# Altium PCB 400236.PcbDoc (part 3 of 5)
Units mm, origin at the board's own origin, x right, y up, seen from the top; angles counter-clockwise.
Board outline 136.53 x 63.5 mm, 4 copper layers (Top Layer, Mid-Layer 1, Mid-Layer 2, Bottom Layer), stack 1.505 mm thick; 340 components, 230 nets, 1369 pads, 1292 vias.
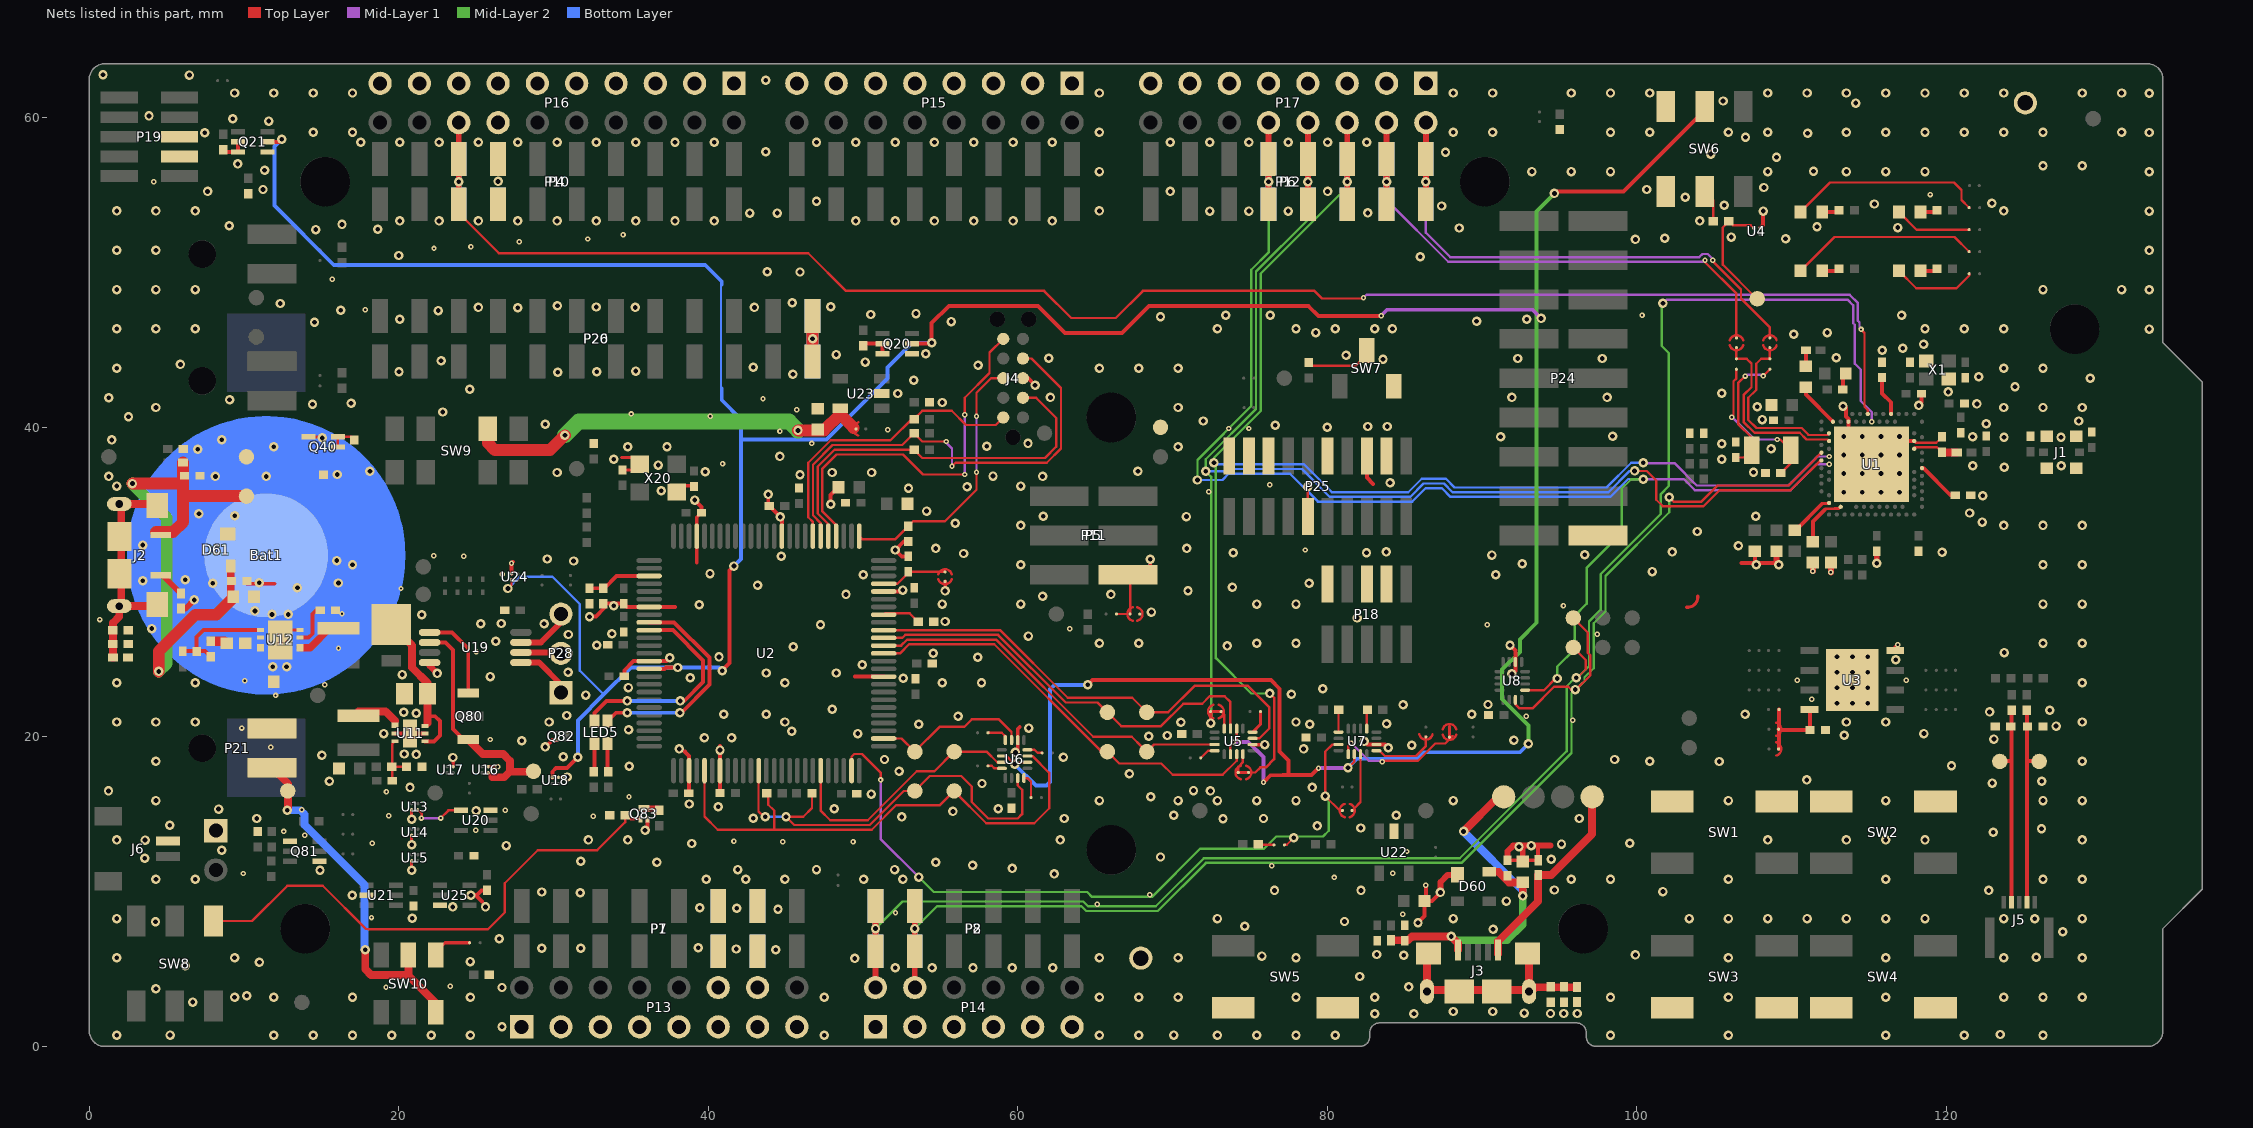
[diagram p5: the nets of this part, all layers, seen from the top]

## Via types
v1: diameter 0.61, hole 0.305, Top Layer to Bottom Layer, tented both sides, 1088 vias
v2: diameter 0.35, hole 0.15, Top Layer to Mid-Layer 1, tented both sides, 180 vias
v3: diameter 0.61, hole 0.305, Top Layer to Bottom Layer, 24 vias

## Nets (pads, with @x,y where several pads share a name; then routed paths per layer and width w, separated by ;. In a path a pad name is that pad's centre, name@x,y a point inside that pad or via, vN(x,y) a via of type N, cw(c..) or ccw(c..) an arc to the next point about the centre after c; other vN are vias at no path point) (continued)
GND: Bat1.2 C1.2 C2.2 C3.1 C4.1 C5.2 C6.2 C7.2 C8.2 C9.2 C10.1 C11.2 C12.2 C13.2 C14.2 C15.1 C16.2 C17.1 C18.1 C19.2 C20.2 C21.2 C22.2 C23.2 C24.1 C25.1 C26.1 C27.1 C28.1 C29.2 C30.2 C31.1 C32.2 C33.1 C34.1 C35.1 C36.1 C37.1 C38.1 C39.1 C40.1 C41.1 C42.1 C43.1 C44.1 C45.1 C46.2 C47.1 C48.1 C49.1 C50.1 C51.1 C52.2 C60.1 C61.1 C62.1 C63.2 C64.1 C65.1 C66.1 C67.1 C68.1 C69.1 C80.1 C82.1 C83.1 C84.1 C85.1 C86.1 C88.1 C89.1 C90.1 C91.1 C92.1 C93.1 D60.1 D61.1 FB62.2 FB63.2 FB64.2 FB65.2 J1.2 J4.3 J6.1 P1.6 P1.7 P4.7 P7.6 P7.7 P10.7 P13.1 P13.3 P13.5 P13.7 P13.9 P13.11 P13.12 P13.13 P13.14 P13.15 P14.1 P14.3 P14.5 P14.7 P14.9 P14.11 P15.1 P15.3 P15.5 P15.7 P15.9 P15.11 P15.13 P15.15 P16.1 P16.3 P16.5 P16.7 P16.9 P16.11 P16.13 P16.14 P16.15 P16.17 P16.19 P17.1 P17.3 P17.5 P17.7 P17.9 P17.11 P17.13 P17.15 P18.3 P18.5 P18.9 P19.3 P19.5 P21.1 P24.18 P25.3 P25.5 P25.9 P25.15 P25.17 P25.19 P27.1 Q20.1 Q21.1 Q40.1 Q81.1 Q81.4 Q82.2 Q83.2 R23.1 R25.1 R26.2 R27.1 R30.1 R40.2 R62.1 R63.1 R67.2 R81.1 R84.1 R85.2 R88.2 R92.2 R94.2 SB30.2 SB32.1 SW1.1 SW2.1 SW3.1 SW4.1 SW5.1 SW6.1 SW6.4 SW7.1 TP12.1 TP39.1 TP40.1 TP41.1 U1.74 U1.B7 U1.F23 U2.3 U2.7 U2.35 U2.46 U2.61 U2.72 U2.82 U2.89 U3.4 U3.9 U4.B1 U5.6 U6.6 U7.6 U8.6 U11.2 U11.5 U11.7 U12.4 U12.8 U12.9 U12.11 U13.B1 U14.B1 U15.B1 U16.B1 U17.B1 U18.B1 U19.4 U20.3 U21.2 U22.2 U23.2 U24.B1 U25.3 X1.2 X1.4 X20.2 X20.4 | length 91.7
  Top Layer w0.145: U1.F23@117.914,39.117 118.019,39.012 119.335,39.012 C3.1@119.715,39.393
  Top Layer w0.203: U12.11@12.344,25.984 U12.11@12.994,26.634 ; U12.11@12.994,26.914 U12.4@13.614,26.914 ; Q40.1@14.163,39.385 15.047,39.385 v3@15.062,39.37 ; v1(20.831,11.382) U15.B1@20.831,11.992 ; v1(20.831,13.033) U14.B1@20.831,13.643 ; v1(20.831,14.684) U13.B1@20.831,15.294 ; U17.B1@23.517,18.082 v1@23.517,18.691 ; U16.B1@25.778,18.082 v2(26.387,18.082) ; U18.B1@30.319,17.386 30.859,17.386 v1(30.884,17.412) ; 34.392,38.049 35.145,38.049 X20.2@35.575,37.619 35.21,37.254 C29.2@34.458,37.254 ; 103.207,28.382 ccw(c103.276,29.032) 103.927,29.1
  Top Layer w0.229: v1(43.866,35.67) 43.866,34.999 C34.1@43.94,34.925 ; v1(55.296,29.436) SB30.2@55.296,30.045 ; U5.6@75.157,19.507 v1(75.946,19.507)
  Top Layer w0.25: U11.2@19.751,20.218 U11.7@20.726,20.218 U11.5@21.701,20.218 ; U24.B1@27.283,30.553 v2(27.283,31.22) v2@27.381,31.318 ; v1(82.372,19.71) 82.572,19.51 U7.6@83.165,19.51 83.715,19.51 v1(83.922,19.304) ; P25.5@82.55,38.145 82.55,36.754 82.956,36.347 ; U4.B1@107.944,52.881 107.948,52.881 108.15,53.083 v1@108.15,53.997 ; v1@113.506,41.26 113.506,40.699 113.664,40.541 U1.B7@113.664,40.367 U1.74@113.664,39.117 ; U1.74@115.164,37.617 116.664,39.117 U1.F23@117.914,39.117
  Top Layer w0.254: C65.1@10.193,29.997 10.193,29.896 11.966,29.896 ; v1(24.663,9.779) 24.968,9.779 ; 25.375,9.373 24.968,9.779 ; C90.1@25.705,10.092 25.357,10.092 25.044,9.779 24.968,9.779 ; v1(29.464,19.355) 29.925,19.816 Q82.2@30.155,19.816 ; v1@32.451,27.788 32.731,27.788 33.289,28.346 33.289,28.608 C28.1@34.534,28.608 34.742,28.4 37.843,28.4 ; C25.1@34.604,23.9 C25.1@34.577,23.927 34.577,24.309 35.168,24.9 37.295,24.9 v1(37.516,25.121) ; v1(35.916,13.97) 36.064,14.119 Q83.2@36.064,14.687 ; X20.4@37.963,36.228 C30.2@39.081,36.228 ; 38.506,19.05 38.506,19.025 38.754,18.777 U2.3@38.754,17.825 ; C31.1@38.742,16.358 U2.3@38.742,17.813 ; v1(39.116,35.306) 39.555,34.867 C32.2@39.555,34.493 39.254,34.192 39.254,31.253 ; C33.1@40.75,16.383 40.754,16.388 U2.7@40.754,17.825 v1@40.754,19.418 ; C34.1@43.94,34.925 v1@44.6,34.265 ; U2.61@44.754,32.975 v1@44.754,34.055 ; v1(47.904,35.027) 47.904,35.635 C38.1@48.413,36.144 ; 49.481,23.9 U2.35@51.329,23.9 ; U2.46@51.329,29.4 52.479,29.4 v1(52.568,29.489) ; C44.1@52.924,31.666 52.5,31.666 v1(52.085,32.08) 52.627,32.622 R67.2@52.924,32.622 ; v1(59.842,18.999) 59.992,19.148 U6.6@59.992,19.792 59.992,20.52 60.122,20.65 ; J4.3@60.325,43.18 60.655,43.18 v1(61.112,42.723) ; v1(85.852,8.001) 86.273,8.422 C91.1@86.273,9.398 ; v2(86.36,10.414) 86.36,9.485 C91.1@86.273,9.398 ; v1(87.303,9.953) 86.748,9.398 C91.1@86.273,9.398 ; C62.1@91.632,12.032 92.544,12.032 FB62.2@93.65,12.032 ; v1(91.796,25.933) 92.148,25.581 U8.6@92.148,24.847 92.148,24.254 v1@91.973,24.079 ; FB62.2@93.614,12.033 93.614,12.979 ; 106.756,31.242 v1@109.093,31.242 ; C6.2@107.613,31.992 107.613,31.168 v1@107.664,31.117 ; C16.2@113.301,42.443 113.301,43.294 C15.1@113.489,43.481 ; U3.4@116.689,25.578 116.689,25.808 v2(116.84,25.959) ; v1(118.214,41.417) 118.389,41.592 C12.2@118.389,42.167
  Top Layer w0.381: FB63.2@5.933,28.304 6.231,28.304 v3(6.782,28.854) ; U19.4@21.993,24.806 21.993,24.591 v1(22.479,24.105) ; v1(87.303,9.953) 87.303,10.62 87.772,11.09 D60.1@88.402,11.09 ; C62.1@91.632,12.032 91.632,12.613 91.999,12.979 94.412,12.979 ; C61.1@92.544,12.032 C61.1@92.623,11.953 v1@92.623,12.979 ; C19.2@109.014,31.992 109.014,31.267 v1(109.164,31.117) ; v2@111.364,30.709 C20.2@111.364,31.267 ; v2@112.539,30.632 C21.2@112.539,31.267 ; C7.2@115.49,31.992 115.49,31.221 v1(115.494,31.217)
  Top Layer w0.635: R81.1@7.899,26.179 C83.1@8.76,26.179
  other v1: 1.772,0.723 11.932,0.723 14.472,0.723 17.012,0.723 19.552,0.723 22.092,0.723 24.632,0.723 47.492,0.723 65.272,0.723 67.812,0.723 72.892,0.723 75.432,0.723 77.972,0.723 80.512,0.723 98.292,0.723 105.912,0.723 116.072,0.723 121.152,0.723 126.232,0.723 5.223,0.737 70.079,0.737 123.463,0.774 26.67,1.27 83.052,2.12 85.592,2.12 94.412,2.134 95.275,2.134 96.139,2.134 92.71,2.159 88.138,2.261 90.678,2.261 6.696,2.87 9.392,3.187 11.932,3.187 17.012,3.187 24.632,3.187 47.492,3.187 65.272,3.187 67.812,3.187 70.352,3.187 77.972,3.187 83.052,3.187 98.292,3.187 105.912,3.187 116.072,3.187 123.692,3.187 126.232,3.187 128.772,3.187 10.185,3.277 4.309,3.734 26.67,3.81 85.261,3.847 82.093,4.521 52.07,5.08 54.458,5.08 57.099,5.08 59.639,5.08 62.255,5.08 6.214,5.207 10.998,5.436 24.613,5.486 49.454,5.69 1.772,5.727 9.392,5.727 65.272,5.727 70.352,5.727 77.972,5.727 105.912,5.727 116.072,5.727 123.692,5.727 128.772,5.727 125.806,5.766 75.768,5.842 84.938,5.893 99.898,5.918 83.185,5.944 44.348,6.248 41.808,6.299 29.235,6.35 31.75,6.35 39.345,6.375 26.492,6.96 127.508,7.417 90.703,7.569 74.651,7.772 4.283,8.052 81.102,8.077 1.772,8.267 72.892,8.267 88.132,8.267 103.372,8.267 105.912,8.267 108.452,8.267 110.992,8.267 113.532,8.267 116.072,8.267 118.612,8.267 123.692,8.267 125.705,8.255 128.772,8.267 20.879,8.28 44.501,8.865 41.834,8.941 39.446,8.966 23.495,9.017 25.603,9.017 91.567,9.398 16.993,9.779 31.725,9.931 29.235,9.982 101.676,10.008 76.581,10.084 82.169,10.084 122.733,10.084 94.666,10.109 4.312,10.807 6.852,10.807 39.872,10.807 42.412,10.807 44.952,10.807 50.032,10.807 52.572,10.807 95.752,10.807 98.292,10.807 105.912,10.807 116.072,10.807 126.232,10.807 128.772,10.807 62.357,11.151 14.91,11.379 41.91,11.43 46.99,11.43 52.032,11.43 59.639,11.506 57.074,11.709 36.678,11.897 54.686,11.913 31.75,11.963 94.463,12.09 3.581,12.167 69.215,12.243 8.56,12.675 92.38,12.903 26.949,12.979 93.167,12.979 95.123,13.081 38.938,13.117 99.543,13.132 1.772,13.347 3.607,13.335 32.252,13.347 34.792,13.347 62.732,13.347 108.452,13.347 113.532,13.347 116.072,13.347 118.612,13.347 128.772,13.347 123.012,13.843 126.136,14.072 82.149,14.115 79.35,14.249 5.207,14.3 73.254,14.707 10.82,14.732 42.901,14.742 62.992,14.732 75.87,14.732 96.266,14.732 52.502,14.834 70.079,14.935 84.455,14.935 55.804,15.189 24.994,15.24 8.357,15.342 48.133,15.367 58.725,15.367 40.64,15.494 38.772,15.666 4.312,15.887 65.272,15.887 70.352,15.887 72.892,15.887 75.432,15.887 77.972,15.887 88.132,15.887 105.912,15.887 116.072,15.887 126.232,15.887 128.772,15.887 68.58,16.129 50.521,16.307 1.245,16.51 72.441,16.51 71.349,16.535 20.726,16.739 79.019,16.739 57.683,16.993 122.961,17.018 15.519,17.145 126.162,17.145 110.973,17.221 67.208,17.628 52.324,17.78 34.9,18.11 120.32,18.136 4.312,18.427 100.832,18.427 105.308,18.415 128.772,18.427 51.384,18.542 98.552,18.542 23.499,18.673 62.941,18.694 30.632,18.72 15.037,18.821 21.133,18.872 20.345,18.898 40.754,19.152 38.115,19.228 78.461,19.228 85.446,19.456 27.94,19.761 92.05,19.787 123.063,19.863 39.751,19.939 41.504,19.939 68.453,20.041 69.647,20.091 113.386,20.117 19.025,20.218 49.647,20.218 118.542,20.218 45.392,20.365 34.849,20.472 60.706,20.574 127.076,20.701 53.594,20.828 78.867,20.828 83.82,20.853 1.772,20.967 4.312,20.967 6.852,20.967 29.712,20.967 44.952,20.967 70.536,20.955 77.972,20.967 113.532,20.967 116.072,20.967 128.772,20.967 56.134,21.336 30.861,21.387 40.996,21.463 43.739,21.463 89.332,21.463 106.985,21.463 21.133,21.539 20.32,21.59 122.784,21.615 126.67,21.717 48.006,21.793 84.887,22.073 90.373,22.098 112.919,22.173 113.919,22.173 114.919,22.173 32.08,22.708 77.673,22.758 79.705,23.114 112.919,23.173 113.919,23.173 114.919,23.173 34.839,23.19 1.772,23.507 6.852,23.507 44.952,23.507 55.112,23.507 57.652,23.507 128.772,23.507 52.593,23.8 38.837,23.825 25.908,23.901 20.218,24.028 91.923,24.079 43.739,24.13 48.26,24.13 112.919,24.173 113.919,24.173 114.919,24.173 30.937,24.181 49.952,24.663 116.713,24.994 57.404,25.146 40.691,25.171 112.919,25.173 113.919,25.173 114.919,25.173 54.526,25.41 123.723,25.451 45.494,25.826 73.533,25.883 32.791,25.933 65.272,26.047 67.812,26.047 75.432,26.047 77.972,26.047 126.232,26.047 128.772,26.047 26.264,26.187 60.681,26.518 30.963,26.619 33.772,26.67 47.246,27.248 25.298,27.305 29.388,27.305 26.619,27.331 55.296,27.457 81.915,27.686 32.324,27.762 21.488,27.889 68.631,28.067 33.899,28.473 39.421,28.55 55.112,28.587 60.192,28.587 75.432,28.587 77.972,28.587 126.232,28.587 128.772,28.587 61.595,29.083 48.895,29.21 66.015,29.21 70.993,29.439 73.863,29.667 43.18,29.794 78.816,29.921 50.013,30.48 90.881,30.48 40.107,30.556 100.99,30.683 17.012,31.127 60.192,31.127 107.714,31.117 126.232,31.127 128.772,31.127 92.583,31.191 31.293,31.369 29.591,31.496 44.719,31.674 90.627,31.75 96.622,31.775 56.49,31.852 73.914,31.902 82.525,31.902 119.71,31.928 83.795,31.953 102.286,31.953 54.686,32.182 70.917,32.182 106.553,32.36 103.886,33.274 60.192,33.667 123.692,33.667 126.232,33.667 128.772,33.667 55.956,33.807 122.301,33.884 44.643,34.214 70.891,34.239 107.68,34.258 61.646,34.265 121.488,34.468 54.102,34.595 122.339,35.592 113.364,35.817 114.564,35.817 115.764,35.817 116.964,35.817 36.957,35.916 52.934,36.068 56.718,36.17 1.772,36.207 60.192,36.207 84.049,36.424 1.27,36.83 61.595,36.83 58.395,36.855 45.923,36.932 113.364,37.017 114.564,37.017 115.764,37.017 116.964,37.017 30.226,37.084 47.996,37.084 50.546,37.084 107.528,37.103 39.802,37.135 67.759,37.17 123.739,37.416 121.689,37.517 127.422,37.517 36.769,37.567 33.899,37.948 105.486,37.948 44.628,38.125 113.364,38.217 114.564,38.217 115.764,38.217 116.964,38.217 108.664,38.617 11.932,38.747 34.792,38.747 37.332,38.747 70.352,38.747 57.988,38.786 105.486,38.938 60.655,38.964 1.448,39.192 123.714,39.367 127.397,39.367 91.186,39.395 113.364,39.417 114.564,39.417 115.764,39.417 116.964,39.417 121.681,39.395 98.425,39.421 79.985,40.005 82.601,40.056 83.871,40.056 76.632,40.132 29.464,40.206 122.57,40.234 71.984,40.411 128.549,40.411 108.087,40.506 2.54,40.691 22.835,40.996 4.312,41.287 70.352,41.287 123.692,41.287 126.232,41.287 128.772,41.287 107.764,41.342 113.313,41.368 14.427,41.504 121.964,41.517 16.916,41.554 55.109,41.61 9.068,41.783 1.27,41.91 62.103,41.935 91.923,41.935 98.069,41.935 52.248,42.189 105.486,42.215 120.114,42.292 24.587,42.469 124.426,42.617 53.264,43.053 129.286,43.18 122.089,43.267 45.466,43.434 30.277,43.561 20.015,43.586 32.791,43.586 35.306,43.637 1.772,43.827 65.272,43.827 67.812,43.827 70.352,43.827 123.692,43.827 126.232,43.827 42.901,43.891 57.429,44.018 5.893,44.069 50.14,44.221 22.733,44.298 83.591,44.399 92.304,44.45 97.765,44.45 62.001,44.475 112.878,44.501 81.204,44.653 48.26,44.704 54.042,44.759 115.845,44.992 117.164,45.117 118.516,45.364 110.134,46.025 79.248,46.126 112.293,46.126 1.772,46.367 4.312,46.367 6.852,46.367 72.892,46.367 77.972,46.367 80.512,46.367 83.052,46.367 118.612,46.367 121.152,46.367 123.692,46.367 133.096,46.355 84.201,46.38 14.554,46.787 55.702,46.838 89.637,46.863 20.066,46.99 92.888,46.99 69.215,47.142 73.431,47.244 76.302,47.244 117.094,47.244 50.495,47.295 53.416,47.356 22.555,47.549 16.256,47.574 27.686,47.727 25.146,47.752 35.281,47.752 42.977,47.752 32.766,47.777 47.904,47.803 30.251,47.854 12.344,48.006 45.415,48.057 1.772,48.907 4.312,48.907 6.852,48.907 126.232,48.907 131.312,48.907 133.096,48.895 45.923,50.038 43.815,50.063 86.004,51.029 19.99,51.105 1.772,51.447 4.312,51.447 133.096,51.435 99.898,52.146 109.601,52.197 101.803,52.222 106.096,52.299 14.63,52.781 18.644,52.807 88.519,52.883 116.84,52.908 111.633,52.959 9.042,53.035 16.332,53.111 20.066,53.34 22.606,53.34 25.146,53.34 27.686,53.34 30.226,53.34 32.766,53.34 35.306,53.34 37.846,53.34 40.386,53.34 49.53,53.34 52.07,53.34 54.61,53.34 57.15,53.34 59.69,53.34 62.23,53.34 104.064,53.34 42.672,53.848 44.45,53.848 82.601,53.858 1.772,53.987 4.312,53.987 6.852,53.987 65.272,53.987 72.39,53.975 74.93,53.975 77.47,53.975 108.15,53.975 123.692,53.987 133.096,53.975 87.376,54.305 105.639,54.356 115.341,54.432 122.936,54.483 46.99,54.61 103.124,54.864 7.645,55.245 69.85,55.245 80.01,55.245 11.227,55.372 100.635,55.372 108.204,55.499 26.416,55.89 65.272,56.527 93.212,56.527 95.752,56.527 98.292,56.527 108.452,56.527 113.532,56.527 116.072,56.527 118.612,56.527 133.096,56.515 111.404,56.54 11.328,56.617 126.232,56.908 128.772,56.908 9.601,57.023 109.017,57.455 104.775,57.658 87.63,57.785 43.713,57.81 17.551,58.42 20.066,58.42 22.606,58.42 25.146,58.42 27.686,58.42 30.226,58.42 32.766,58.42 35.306,58.42 37.846,58.42 40.386,58.42 46.99,58.42 49.53,58.42 52.07,58.42 54.61,58.42 57.15,58.42 59.69,58.42 62.23,58.42 69.85,58.42 72.39,58.42 74.93,58.42 77.47,58.42 80.01,58.42 82.55,58.42 107.01,58.75 111.023,59.004 7.467,59.03 14.472,59.067 17.012,59.067 65.272,59.067 88.132,59.067 90.672,59.067 98.292,59.067 100.832,59.067 105.912,59.067 108.452,59.067 113.532,59.067 116.072,59.067 118.612,59.067 121.152,59.067 123.692,59.067 126.232,59.067 131.312,59.067 133.096,59.055 11.608,59.792 9.271,59.944 3.861,60.122 114.144,60.957 105.562,61.087 9.392,61.607 11.932,61.607 14.472,61.607 17.012,61.607 65.272,61.607 88.132,61.607 90.672,61.607 95.752,61.607 98.292,61.607 100.832,61.607 108.452,61.607 110.992,61.607 113.532,61.607 116.072,61.607 118.612,61.607 121.152,61.607 123.692,61.607 128.772,61.607 131.312,61.607 133.096,61.595 43.713,62.433 6.477,62.763 0.889,62.789
  other v2: 19.177,3.835 23.325,3.886 18.237,8.331 84.861,8.534 52.095,8.636 65.126,9.195 68.529,9.804 80.442,10.922 9.957,11.176 84.226,11.201 76.403,11.684 85.141,12.598 18.288,13.132 44.806,13.233 49.352,13.233 41.656,13.259 13.919,13.64 12.573,13.894 24.968,13.97 32.563,14.884 19.355,14.91 26.873,15.265 13.741,15.291 34.874,16.129 19.202,16.459 11.735,19.329 25.908,19.837 9.855,20.574 95.86,21.082 92.837,21.336 111.303,22.428 12.04,22.682 15.215,23.368 10.058,23.622 110.363,23.673 117.399,23.673 24.994,25.502 16.104,25.73 97.434,26.634 63.348,27 90.322,27.254 0.686,27.584 16.332,27.965 95.25,28.473 20.142,29.591 26.68,30.505 112.522,30.632 111.354,30.709 24.206,31.674 22.25,31.699 78.562,32.08 72.339,35.839 76.276,36.297 40.919,37.643 46.685,38.964 44.628,39.751 51.587,39.853 73.635,39.929 74.93,39.929 40.132,40.716 35.027,40.869 45.72,41.148 43.536,41.859 100.33,47.244 17.831,47.6 15.697,49.581 22.276,51.562 24.663,51.664 27.788,51.994 32.207,52.172 34.493,52.451 118.948,55.042 4.166,55.88
  other v3: 11.862,24.536 12.751,24.536 4.039,27 11.811,27.915 12.852,27.915 10.708,28.144 13.452,29.642 7.976,29.921 10.988,29.959 16.104,29.947 3.454,30.084 6.212,30.151 16.002,31.394 3.454,32.395 9.398,34.3 7.087,34.427 8.153,36.83 11.43,36.83 16.027,36.957 18.136,37.16 7.01,38.583 8.56,39.202 15.062,39.319
I\F\_\O\F\F\: Q20.2 Q21.2 SW6.2 U2.90 U5.2 U5.10 U6.2 U6.10 U7.2 U18.B2 U24.B2 | length 259.6
  Top Layer w0.152: Q21.2@11.516,58.445 12.04,58.445 ; v1(27.051,29.591) 27.283,29.823 U24.B2@27.283,30.153 ; U6.10@58.967,18.767 59.26,18.767 59.66,18.367 U6.2@60.617,18.367 ; U5.2@73.732,18.882 73.732,19.478 v2(73.907,19.653) 74.132,19.878 U5.10@74.132,20.532 ; v1(81.331,18.009) 81.74,18.418 U7.2@81.74,18.885
  Top Layer w0.254: 12.04,58.445 12.268,58.445 v1(12.446,58.623) ; U18.B2@29.919,17.386 29.919,17.752 30.166,17.999 30.877,17.999 v1(31.572,18.694) ; U2.90@36.179,24.4 37.163,24.4 37.248,24.486 v1(38.024,24.486) ; v1(40.894,24.282) 41.377,24.765 41.377,30.759 v1(41.656,31.039) ; Q20.2@53.155,45.415 54.381,45.415 v1(54.432,45.466) 54.432,46.736 55.55,47.854 61.295,47.854 63.047,46.101 66.726,46.101 68.478,47.854 78.764,47.854 79.416,47.201 83.456,47.201 v2(83.469,47.214) ; v1(64.516,23.368) 64.823,23.675 76.35,23.675 76.913,23.112 76.913,19.048 77.495,18.466 77.495,17.533 ; v2(75.87,17.069) 76.327,17.526 77.128,17.526 77.135,17.533 77.495,17.533 ; v2(79.426,17.983) 78.976,17.533 77.495,17.533 ; v1(94.666,55.118) 94.793,55.245 99.129,55.245 SW6.2@104.369,60.484
  Mid-Layer 1 w0.254: v2@73.932,19.678 74.886,19.678 75.87,18.694 v2(75.87,17.069) ; v2(79.426,17.983) 81.305,17.983 v1(81.331,18.009) ; v2(83.469,47.214) 83.854,47.6 93.243,47.6 v1(93.802,47.041)
  Mid-Layer 2 w0.254: v1(92.989,19.558) 92.989,20.752 91.288,22.454 91.288,24.359 92.431,25.502 92.431,26.309 93.497,27.376 v1@93.497,47.041 ; v1(93.802,47.041) v1@93.497,47.041 ; v1(94.666,55.118) 93.497,53.95 v1@93.497,47.041
  Bottom Layer w0.152: v1(27.051,29.591) 27.805,30.345 29.929,30.345 31.699,28.575 31.699,24.272 33.238,22.733 ; 40.818,42.52 40.818,49.224
  Bottom Layer w0.254: v1(12.446,58.623) 11.963,58.141 11.963,54.331 15.799,50.495 39.802,50.495 40.869,49.428 40.869,49.224 ; v1(31.572,18.694) 31.572,21.067 33.238,22.733 34.991,24.486 v1(38.024,24.486) 40.691,24.486 v1(40.894,24.282) ; 40.869,42.52 40.869,41.758 42.113,40.513 42.113,39.268 ; v1(41.656,31.039) 42.113,31.496 42.113,39.268 ; v1(54.432,45.466) 53.162,45.466 51.575,43.878 51.575,43.149 47.643,39.218 42.164,39.218 42.113,39.268 ; v1(59.792,18.237) 61.163,16.866 61.849,16.866 62.078,17.094 62.078,23.089 62.357,23.368 v1(64.516,23.368) ; v1(81.331,18.009) 81.915,18.593 85.827,18.593 86.245,19.011 92.443,19.011 v1(92.989,19.558)
IMCU_BOOT: SB46.2 SB65.1 U2.24 U7.15 | length 48.6
  Top Layer w0.152: U2.24@49.254,17.825 49.254,18.723 49.428,18.898 49.936,18.898 51.13,17.704 v2(51.13,17.221) ; SB65.1@77.224,13.03 77.368,13.03 v1(77.826,13.487) ; v1(79.858,16.18) v1@79.865,16.172 ; v1@79.916,16.172 v1@80.035,16.172 ; U7.15@80.715,19.51 80.326,19.51 79.865,19.05 v1@79.865,16.172 ; SB46.2@80.968,15.24 80.797,15.24 80.793,15.244 v1@79.865,16.172
  Mid-Layer 1 w0.152: v2(51.13,17.221) 51.13,13.411 v1(53.594,10.947)
  Mid-Layer 2 w0.152: v1(53.594,10.947) 54.559,9.982 64.478,9.982 64.794,9.667 68.659,9.667 71.768,12.776 75.903,12.776 76.69,13.564 79.706,13.564 80.086,13.944 80.086,15.951 v1(79.858,16.18)
IMCU_CTS: TP1.1 U2.38 U5.3 | length 27
  Top Layer w0.152: U2.38@51.329,25.4 52.389,25.4 52.973,25.984 53.67,25.984 58.471,25.984 TP1.1@65.405,19.05 ; TP1.1@65.786,19.05 66.548,18.288 69.266,18.288 70.002,17.551 73.228,17.551 74.139,18.463 U5.3@74.139,18.885
IMCU_RESET: J4.10 R66.1 U2.57 | length 19.4
  Top Layer w0.152: U2.57@46.754,32.975 46.754,33.894 46.457,34.192 46.457,37.717 47.907,39.167 51.773,39.167 R66.1@53.221,40.615 ; R66.1@53.297,40.538 53.831,41.072 55.726,41.072 56.64,40.157 58.572,40.157 J4.10@59.055,40.64
IMCU_RTS: TP3.1 U2.39 U5.15 | length 24.3
  Top Layer w0.152: U2.39@51.329,25.9 52.458,25.9 52.848,26.29 53.035,26.29 56.972,26.29 56.974,26.289 58.597,26.289 64.871,20.015 67.361,20.015 TP3.1@67.988,19.388 ; TP3.1@68.326,19.05 68.786,19.51 U5.15@72.714,19.51
IMCU_RXD: TP2.1 U2.40 U5.11 | length 27.6
  Top Layer w0.152: U2.40@51.329,26.4 52.527,26.4 52.722,26.595 58.722,26.595 63.092,22.225 65.151,22.225 TP2.1@65.786,21.59 66.675,20.701 69.247,20.701 70.695,22.149 71.907,22.149 72.39,22.631 73.355,22.631 73.732,22.254 U5.11@73.732,20.532
IMCU_TCKS: J4.4 R65.1 U2.56 | length 30.9
  Top Layer w0.152: U2.56@47.254,32.975 47.254,33.825 46.761,34.318 46.761,37.59 48.033,38.862 52.531,38.862 53.293,39.624 53.827,39.091 v2@55.397,39.091 ; v2(55.745,37.49) 55.974,37.719 61.87,37.719 62.786,38.635 62.786,42.547 60.884,44.45 J4.4@60.325,44.45
  Mid-Layer 1 w0.152: v2@55.397,39.091 55.397,38.989 55.745,38.641 v2(55.745,37.49)
  other v2: 55.372,39.091
IMCU_TDIS: J4.8 R67.1 U2.51 | length 17.4
  Top Layer w0.152: U2.51@49.754,32.975 49.963,32.766 52.068,32.766 R67.1@52.924,33.622 53.236,33.934 55.296,33.934 57.328,35.966 v2(57.328,37.109) ; v2(57.328,40.716) 57.328,42.241 58.267,43.18 J4.8@59.055,43.18
  Mid-Layer 1 w0.152: v2(57.328,37.109) v2(57.328,40.716)
IMCU_TDOS: J4.6 U2.54 | length 24.6
  Top Layer w0.152: U2.54@48.254,32.975 48.254,33.687 47.371,34.571 47.371,37.338 48.285,38.252 52.578,38.252 53.873,36.957 v2(56.566,36.957) ; v2@56.566,40.767 56.566,41.91 58.166,43.51 58.166,44.831 J4.6@59.055,45.72
  Mid-Layer 1 w0.152: v2(56.566,36.957) v2@56.566,40.767
  other v2: 56.566,40.818
IMCU_TMSS: J4.2 R64.1 U2.55 | length 25.7
  Top Layer w0.152: U2.55@47.754,32.975 47.754,33.756 47.066,34.444 47.066,37.464 48.159,38.557 53.293,38.557 53.827,38.024 61.747,38.024 62.484,38.76 62.484,40.604 61.178,41.91 J4.2@60.325,41.91
IMCU_TXD: TP4.1 U2.41 U5.7 | length 31.1
  Top Layer w0.152: U2.41@51.329,26.9 58.848,26.9 63.218,22.53 67.386,22.53 TP4.1@68.326,21.59 69.705,21.59 71.434,23.319 74.826,23.319 76.251,21.895 76.251,20.566 75.592,19.907 U5.7@75.157,19.907
N\R\F\_\O\N\L\Y\: R3.1 TP22.1 U4.B2 | length 7.9
  Top Layer w0.152: U4.B2@107.544,52.876 107.357,53.063 106.187,53.063 R3.1@105.935,53.315 105.537,52.916 105.537,50.516 107.743,48.311 TP22.1@107.772,48.311
NetC3_2: C3.2 L1.1 U1.H23 | length 2.9
  Top Layer w0.145: U1.H23@117.914,38.617 118.019,38.722 119.384,38.722 119.718,38.388 C3.2@119.723,38.383
  Top Layer w0.508: C3.2@119.718,38.388 L1.1@120.612,38.388
NetC9_1: C9.1 U1.N24 | length 2.9
  Top Layer w0.25: U1.N24@118.414,37.367 118.5,37.367 120.25,35.617 C9.1@120.564,35.617
NetC13_1: C13.1 U1.A18 | length 2.6
  Top Layer w0.25: C13.1@115.839,43.217 115.839,42.2 116.414,41.625 U1.A18@116.414,40.867
NetC17_2: C17.2 SB2.1 X2.1 | length 8.3
  Top Layer w0.152: C17.2@106.385,38.05 106.921,38.05 107.421,38.55 107.421,39.34 106.537,40.224 106.537,42.86 v2(106.995,43.317) ; v2@107.02,43.317 v2@107.045,43.291 ; v2(108.153,43.325) SB2.1@108.585,43.757
  Mid-Layer 1 w0.152: v2@107.104,43.401 108.077,43.401 v2(108.153,43.325)
NetC18_2: C18.2 SB1.1 X2.2 | length 9.6
  Top Layer w0.152: v2(106.121,40.665) 106.24,40.784 106.24,42.983 106.426,43.169 SB1.1@106.426,43.757 ; v2(109.068,39.218) 109.254,39.218 109.921,38.55 X2.2@109.921,38.525 109.921,37.675 C18.2@109.298,37.052
  Mid-Layer 1 w0.152: v2@106.147,40.665 107.594,39.218 v2(109.068,39.218)
NetC20_1: C20.1 U1.AC5 | length 3.6
  Top Layer w0.184: C20.1@111.354,32.614 C20.1@111.354,32.617 ; 112.062,34.608 112.202,34.747 112.254,34.747 112.258,34.743 112.749,34.743 112.755,34.749 113.045,34.749 U1.AC5@113.164,34.867
  Top Layer w0.254: C20.1@111.364,32.617 111.364,33.909 112.112,34.657
NetC27_2: C27.2 R25.2 U2.78 | length 4.1
  Top Layer w0.254: C27.2@32.4,29.608 33.289,29.608 34.081,30.4 U2.78@36.179,30.4
NetC44_2: C44.2 SB30.1 U2.47 | length 4.3
  Top Layer w0.152: U2.47@51.329,29.9 52.214,29.9 52.924,30.609 C44.2@52.924,30.666 54.939,30.666 55.291,30.666 SB30.1@55.296,30.67
NetC49_2: C49.2 SB16.2 SB17.2 SB18.2 U3.8 | length 6
  Top Layer w0.254: SB18.2@109.177,19.228 SB16.2@109.177,21.768 ; SB17.2@109.177,20.523 SB17.2@109.151,20.498 109.202,20.447 C49.2@111.168,20.447 ; U3.8@111.149,21.768 111.168,21.749 C49.2@111.168,20.447 ; C49.2@111.184,20.447 C49.2@111.168,20.447
NetC60_2: C60.2 C61.2 C62.2 D60.4 FB60.1 J3.1 TP15.1 | length 24.3
  Top Layer w0.508: FB60.1@84.106,6.866 85.224,6.866 85.471,7.113 v1(88,7.113) 88.429,6.684 J3.1@88.429,6.232 ; v1(88.798,13.894) TP15.1@91.034,16.129 ; D60.4@90.452,11.29 91.047,11.29 91.733,10.603 C61.2@92.623,10.603 v1(92.623,9.728)
  Mid-Layer 2 w0.508: v1(88,7.113) 88.253,6.86 91.595,6.86 92.623,7.889 v1(92.623,9.728)
  Bottom Layer w0.508: v1(88.798,13.894) 92.623,10.069 v1(92.623,9.728)
NetC63_1: C63.1 C64.2 C65.2 D61.4 FB61.1 J2.1 TP11.1 | length 36.3
  Top Layer w0.508: C64.2@9.144,28.905 D61.4@9.144,31.055
  Top Layer w0.762: v1(2.794,36.373) 5.781,36.373 6.06,36.093 ; J2.1@4.318,33.233 5.41,33.233 6.06,33.884 6.06,35.56 ; v1(4.496,24.232) 4.496,25.538 6.86,27.902 8.217,27.902 C64.2@9.297,28.981 ; FB61.1@6.06,37.734 6.06,36.093 ; TP11.1@10.16,35.56 6.06,35.56 ; 6.06,35.56 6.06,36.093
  Mid-Layer 2 w0.762: v1(2.794,36.373) 5.004,34.163 5.004,24.74 v1(4.496,24.232)
NetC66_2: C66.2 FB64.1 J3.6@86.429,3.557 J3.6@86.529,6.007 J3.6@88.529,3.557 J3.6@90.929,3.557 J3.6@92.929,6.007 J3.6@93.029,3.557 R62.2 | length 14.7
  Top Layer w0.508: J3.6@86.427,6.003 86.427,3.653 J3.6@93.027,3.653 ; J3.6@93.027,3.399 cw(c93.331,3.399) J3.6@93.029,3.434 ; J3.6@93.029,3.303 J3.6@93.029,3.434 ; J3.6@93.029,3.688 J3.6@93.029,6.003 ; J3.6@93.331,3.703 ccw(c93.331,3.399) J3.6@93.029,3.434 ; J3.6@93.331,3.83 FB64.1@96.12,3.83
NetC67_2: C67.2 FB65.1 J2.6@1.944,28.45 J2.6@1.944,30.55 J2.6@1.944,32.95 J2.6@1.944,35.05 J2.6@4.394,28.55 J2.6@4.394,34.95 R63.2 | length 15.1
  Top Layer w0.508: FB65.1@1.546,25.139 1.546,27.378 1.944,27.776 J2.6@1.944,28.45 ; J2.6@2.087,28.434 J2.6@2.071,28.45 ; J2.6@4.521,28.55 4.421,28.45 J2.6@2.071,28.45 ; J2.6@4.521,34.95 4.421,35.05 2.071,35.05 J2.6@2.071,28.45
NetC81_1: C81.1 R80.1 R81.2 U12.7 | length 7.2
  Top Layer w0.254: C81.1@6.045,25.544 R80.1@6.934,25.544 ; R80.1@6.934,25.519 R80.1@6.934,25.544 ; R81.2@7.849,25.179 7.484,25.544 R80.1@6.934,25.544 ; U12.7@11.074,26.914 7.381,26.914 6.934,26.467 R80.1@6.934,25.544
NetC84_2: C84.2 U12.3 | length 2.8
  Top Layer w0.254: U12.3@13.614,26.414 14.175,26.414 14.427,26.666 14.427,27.936 14.685,28.194 C84.2@14.918,28.194
NetC86_2: C86.2 D84.3 U11.4 U11.6 | length 10.3
  Top Layer w0.25: 21.856,21.184 21.857,21.182 21.871,21.168
  Top Layer w0.254: U11.4@21.701,19.718 22.284,19.718 22.657,20.091 22.657,21.031 22.352,21.336 21.857,21.336
  Top Layer w0.508: D84.3@19.507,27.268 20.862,25.914 20.862,24.477 21.857,23.482 C86.2@21.857,22.784 ; 21.857,20.906 21.857,21.182 21.857,21.336 C86.2@21.857,22.76
NetC87_1: C87.1 R82.1 R84.2 U11.3 | length 3.6
  Top Layer w0.152: R82.1@19.55,18.085 R82.1@19.575,18.085 ; C87.1@19.575,17.17 R82.1@19.575,18.085 ; U11.3@19.751,19.718 19.575,19.542 R82.1@19.575,18.085 ; R84.2@20.506,18.085 R82.1@19.575,18.085
NetC92_2: C92.2 SB81.2 SW9.7 U23.5 | length 26.8
  Top Layer w0.762: SW9.7@25.749,39.906 25.749,38.996 26.213,38.532 29.769,38.532 v1(30.734,39.497) ; v1(45.796,39.802) 47.473,39.802 48.51,40.839 ; U23.5@48.51,41.123 48.51,40.839 ; 49.387,39.963 48.51,40.839
  Mid-Layer 2 w1.016: v1(30.734,39.497) 31.623,40.386 45.212,40.386 v1(45.796,39.802)
NetFB62_1: FB62.1 J3.5 TP16.1 | length 13.2
  Top Layer w0.508: J3.5@91.029,5.978 91.029,6.803 93.614,9.387 FB62.1@93.614,11.083 94.457,11.083 97.104,13.73 TP16.1@97.104,16.129
NetFB63_1: FB63.1 J2.5 | length 1.8
  Top Layer w0.381: J2.5@4.619,30.45 4.737,30.45 FB63.1@5.933,29.254
NetL2_1: L2.1 L3.2 | length 1.1
  Top Layer w0.25: L2.1@110.914,43.942 L3.2@110.914,44.992
NetL2_2: L2.2 U1.B3 | length 2.9
  Top Layer w0.25: L2.2@110.914,42.592 110.914,42.117 U1.B3@112.664,40.367
NetL4_2: L4.2 U1.AB2 | length 3.1
  Top Layer w0.203: 111.957,35.063 111.98,35.087 112.383,35.087 U1.AB2@112.414,35.117
  Top Layer w0.25: L4.2@110.189,33.342 L4.2@110.236,33.342 ; L4.2@110.33,33.342 L4.2@110.236,33.342 ; 111.957,35.063 L4.2@110.236,33.342
NetL80_1: L80.1 U12.2 | length 3
  Top Layer w0.457: U12.2@13.614,25.764 14.283,25.764 15.553,27.033 L80.1@16.104,27.033
NetL81_1: L81.1 U11.1 | length 2.6
  Top Layer w0.508: L81.1@17.399,21.649 19.151,21.649 19.751,21.048
NetLED1_1: LED1.1 SB5.2 | length 12.7
  Top Layer w0.152: LED1.1@110.575,53.917 112.48,55.822 120.479,55.822 120.965,55.337 120.965,54.696 SB5.2@121.464,54.197
NetLED1_2: LED1.2 R47.1 | length 1.1
  Top Layer w0.254: LED1.2@111.972,53.917 112.932,53.917 R47.1@113.059,54.044
NetLED2_1: LED2.1 SB6.2 | length 5
  Top Layer w0.152: LED2.1@116.925,53.917 118.067,52.774 120.968,52.774 SB6.2@121.464,52.774
NetLED2_2: LED2.2 R48.1 | length 1.1
  Top Layer w0.254: LED2.2@118.322,53.917 119.257,53.917 R48.1@119.384,54.044
NetLED3_1: LED3.1 SB7.2 | length 12.2
  Top Layer w0.152: LED3.1@110.575,50.107 112.766,52.299 120.517,52.299 SB7.2@121.464,51.352
NetLED3_2: LED3.2 R50.1 | length 1.1
  Top Layer w0.254: LED3.2@111.972,50.107 112.932,50.107 R50.1@113.059,50.234
NetLED4_1: LED4.1 SB8.2 | length 5.5
  Top Layer w0.152: LED4.1@116.925,50.107 118.042,48.99 120.643,48.99 121.464,49.81 SB8.2@121.464,49.93
NetLED4_2: LED4.2 R51.1 | length 1.1
  Top Layer w0.254: LED4.2@118.322,50.107 119.257,50.107 R51.1@119.384,50.234
NetLED5_1: LED5.1 R20.1 | length 1.8
  Top Layer w0.254: R20.1@32.636,17.747 LED5.1@32.636,19.57
NetLED5_2: LED5.2 R21.1 | length 1.8
  Top Layer w0.254: R21.1@33.486,17.747 LED5.2@33.486,19.57
NetP5_6: P5.6 P11.6 SB32.2 SB33.1 | length 5.2
  Top Layer w0.152: SB33.1@66.378,27.94 67.077,27.94 ; P5.6@67.119,30.48 67.252,30.348 67.252,28.293 SB32.2@67.252,27.94
  Top Layer w0.254: P5.6@68.555,30.531 v1(68.555,31.481)
  Bottom Layer w0.254: P11.6@68.555,30.531 v1(68.555,31.481)
NetP20_12: P20.12 P26.12 | length 5.9
  Top Layer w0.762: P20.12@46.736,44.255 P20.12@46.736,47.185
  Bottom Layer w0.762: P26.12@46.736,44.255 v1(46.736,45.72) P26.12@46.736,47.185
NetP21_2: P21.2 SW10.2 SW10.4 TP27.1 | length 23.4
  Top Layer w0.508: P21.2@11.811,18.009 12.852,16.967 12.852,15.316 v1(12.802,15.265) ; v1(17.831,6.248) 17.831,5.004 18.212,4.623 20.574,4.623 ; SW10.2@20.625,5.914 20.625,4.674 20.574,4.623 ; SW10.4@22.375,2.214 22.375,2.822 20.574,4.623
  Bottom Layer w0.508: v1(12.802,15.265) 13.64,15.265 13.919,14.986 13.919,14.305 17.78,10.444 17.78,6.299 v1(17.831,6.248)
NetP28_1: P28.1 U19.5 | length 3.7
  Top Layer w0.381: U19.5@27.893,24.806 29.067,24.806 30.48,23.393 P28.1@30.48,22.86
NetP28_2: P28.2 U19.6 | length 2.6
  Top Layer w0.381: U19.6@27.893,25.456 30.424,25.456 P28.2@30.48,25.4
NetP28_3: P28.3 U19.7 | length 3.7
  Top Layer w0.381: U19.7@27.893,26.106 29.179,26.106 30.48,27.407 P28.3@30.48,27.94
NetQ20_5: Q20.5 Q20.6 R22.2 | length 2
  Top Layer w0.254: R22.2@49.996,45.271 50.14,45.415 Q20.5@51.255,45.415 Q20.6@51.255,44.765
NetQ21_5: Q21.5 Q21.6 R24.2 | length 1.7
  Top Layer w0.254: R24.2@8.661,57.945 8.811,57.795 Q21.6@9.616,57.795 Q21.5@9.616,58.445
NetQ40_5: Q40.5 Q40.6 R41.2 | length 1.8
  Top Layer w0.152: Q40.5@16.063,38.735 Q40.6@16.063,39.385 16.919,39.385 R41.2@17.12,39.184
NetQ80_1: Q80.1 U19.1 | length 5.6
  Top Layer w0.254: U19.1@22.196,26.756 23.434,26.756 24.489,25.701 Q80.1@24.489,22.836
NetQ80_3: Q80.3 TP34.1 U16.A1 U19.2 | length 15
  Top Layer w0.25: U16.A1@25.778,17.682 26.065,17.394
  Top Layer w0.254: U19.2@22.196,26.106 23.018,26.106 23.51,25.614 23.51,20.509 24.182,19.836 Q80.3@24.489,19.836
  Top Layer w0.508: Q80.3@24.489,19.836 25.427,18.898 26.746,18.898 27.178,18.466 27.178,17.755 ; 26.065,17.394 26.818,17.394 27.178,17.755 ; TP34.1@28.651,17.856 28.55,17.755 27.178,17.755
NetQ83_1: Q83.1 R94.1 SW8.4 | length 34.1
  Top Layer w0.152: SW8.4@8.028,8.109 10.522,8.109 12.802,10.389 15.088,10.389 17.882,7.595 18.001,7.595 18.026,7.569 25.756,7.569 26.851,8.664 26.851,10.544 28.981,12.675 32.817,12.675 34.638,14.495 R94.1@34.638,14.935 ; R94.1@34.714,14.961 34.988,14.687 Q83.1@35.614,14.687
NetQ83_3: Q83.3 R93.2 | length 1
  Top Layer w0.381: Q83.3@35.839,15.387 36.701,15.387 R93.2@36.83,15.257
NetR3_2: R3.2 SW6.5 | length 2.2
  Top Layer w0.152: SW6.5@104.369,55.238 104.935,54.671 R3.2@104.935,53.315
NetR4_2: R4.2 SW7.2 | length 4.4
  Top Layer w0.152: R4.2@78.791,44.188 78.985,43.994 81.84,43.994 82.55,44.704 SW7.2@82.55,44.965
NetR30_2: R30.2 U2.43 | length 2.5
  Top Layer w0.152: U2.43@51.329,27.9 51.42,27.991 53.008,27.991 R30.2@53.567,27.432
NetR49_1: R49.1 SB65.2 | length 1
  Top Layer w0.152: R49.1@75.532,13.081 75.582,13.03 SB65.2@76.548,13.03
NetR52_2: R52.2 U7.9 | length 1.2
  Top Layer w0.152: U7.9@82.54,20.535 R52.2@82.54,21.742
NetR53_2: R53.2 U7.13 | length 1.5
  Top Layer w0.152: U7.13@80.715,20.31 R53.2@80.715,21.768
NetSB42_1: SB42.1 U7.1 | length 8.6
  Top Layer w0.152: U7.1@81.34,18.885 81.34,19.415 v2(81.534,19.609) ; v2(83.541,18.39) 83.617,18.466 85.851,18.466 86.965,19.58 87.608,19.58 88.087,20.058
  Mid-Layer 1 w0.152: v2(81.534,19.609) 82.677,18.466 83.464,18.466 v2(83.541,18.39)
NetSB45_1: SB45.1 U7.5 | length 4.2
  Top Layer w0.152: U7.5@83.165,19.11 83.361,19.11 83.701,18.771 85.725,18.771 86.36,19.406 86.36,19.833 SB45.1@86.36,20.008
NetSB46_1: SB46.1 U7.3 | length 3.9
  Top Layer w0.152: SB46.1@81.592,15.24 81.741,15.389 82.14,15.788 U7.3@82.14,18.885
NetSB50_2: SB50.2 U5.16 | length 1.1
  Top Layer w0.152: SB50.2@71.813,18.644 72.28,19.11 U5.16@72.714,19.11
NetSB51_2: SB51.2 U5.4 | length 1.3
  Top Layer w0.152: SB51.2@74.237,17.704 74.237,18.077 74.539,18.38 U5.4@74.539,18.885
NetSB52_2: SB52.2 U5.8 | length 1.6
  Top Layer w0.152: U5.8@75.157,20.307 U5.8@75.164,20.314
  Top Layer w0.203: U5.8@75.164,20.31 75.164,20.314 75.674,20.824 SB52.2@75.674,21.641
NetSB53_2: SB53.2 U5.12 | length 1.2
  Top Layer w0.152: SB53.2@73.134,21.641 73.332,21.443 U5.12@73.332,20.532
NetSB54_2: SB54.2 U6.16 | length 1.6
  Top Layer w0.152: U6.16@60.392,17.342 60.628,17.342 60.851,17.119 SB54.2@60.851,16.078
NetSB55_2: SB55.2 U6.4 | length 1
  Top Layer w0.152: U6.4@60.617,19.167 61.071,19.167 61.265,18.974 SB55.2@61.562,18.974
NetSB56_2: SB56.2 U6.8 | length 1.5
  Top Layer w0.152: SB56.2@58.072,20.269 58.953,20.269 59.192,20.031 U6.8@59.192,19.792
NetSB57_2: SB57.2 U6.12 | length 1
  Top Layer w0.152: SB57.2@58.072,18.136 58.318,18.136 58.487,17.967 U6.12@58.967,17.967 U6.12@58.967,17.937
NetSB58_2: SB58.2 SW10.1 | length 2.6
  Top Layer w0.203: SW10.1@22.375,5.914 22.375,6.093 22.987,6.706 SB58.2@24.58,6.706
NetU13_B2: U13.B2 U20.4 | length 3.4
  Top Layer w0.152: U13.B2@21.231,15.294 21.488,15.037 v2@21.488,14.757 ; v2(22.708,14.757) 23.205,15.255 U20.4@24.018,15.255
  Mid-Layer 1 w0.152: v2(21.463,14.757) v2(22.708,14.757)
NFC1: C46.1 J5.2 R44.1 TP17.1 | length 12.9
  Top Layer w0.25: TP17.1@123.479,18.44 124.198,18.44 ; J5.2@124.198,9.328 124.198,18.44 ; R44.1@124.198,21.463 124.198,18.44
NFC2: C47.2 J5.4 R46.1 TP18.1 | length 12.8
  Top Layer w0.25: J5.4@125.198,9.328 125.198,18.44 ; R46.1@125.198,21.463 125.198,18.44 ; TP18.1@125.909,18.44 125.198,18.44
OB_LED1: LED5.4 U2.84 | length 14.1
  Top Layer w0.254: LED5.4@33.486,21.02 34.031,21.565 v1(34.763,21.565) ; U2.84@36.179,27.4 37.792,27.4 40.071,25.121 40.071,23.38 38.256,21.565 v1(38.166,21.565)
  Bottom Layer w0.254: v1(34.763,21.565) v1(38.166,21.565)
OB_LED2: LED5.3 U2.85 | length 14.1
  Top Layer w0.254: LED5.3@32.636,21.02 32.636,21.546 33.416,22.327 v1(34.763,22.327) ; U2.85@36.179,26.9 37.717,26.9 39.665,24.952 39.665,23.548 38.443,22.327 v1(38.192,22.327)
  Bottom Layer w0.254: v1(34.763,22.327) v1(38.192,22.327)
OB_RESET: TP7.1 U2.27 U6.7 | length 10.3
  Top Layer w0.152: U2.27@51.329,19.9 52.49,19.9 TP7.1@53.34,19.05 54.94,20.65 56.54,20.65 57.023,21.133 58.776,21.133 59.592,20.317 U6.7@59.592,19.792
OB_SWDCLK: R28.2 TP6.1 U2.5 U6.3 | length 34.6
  Top Layer w0.152: U2.5@39.754,17.825 39.754,14.856 40.604,14.006 44.256,14.006 ; R28.2@43.772,16.358 43.875,16.255 43.875,15.621 44.256,15.24 44.256,14.006 ; U6.3@60.617,18.767 60.938,18.767 62.027,17.678 62.027,15.392 61.062,14.427 57.963,14.427 TP6.1@55.88,16.51 54.966,15.596 52.145,15.596 50.555,14.006 44.256,14.006
OB_SWDIO: R29.2 TP5.1 U2.12 U6.15 | length 28.5
  Top Layer w0.152: U2.12@43.254,17.825 43.244,17.814 43.244,15.176 43.576,14.844 v1(43.678,14.844) ; R29.2@46.703,16.358 46.703,15.41 46.137,14.844 v1(45.018,14.844) 45.551,14.31 50.428,14.31 52.628,16.51 TP5.1@53.34,16.51 54.305,17.475 56.337,17.475 57.023,16.789 57.023,15.798 58.089,14.732 59.995,14.732 60.274,15.011 60.274,16.588 59.992,16.87 U6.15@59.992,17.342
  Bottom Layer w0.152: v1(43.678,14.844) v1(45.018,14.844)
OB_SWO: TP8.1 U2.20 U6.11 | length 16.7
  Top Layer w0.152: U2.20@47.254,17.825 47.254,15.24 47.879,14.615 50.302,14.615 53.467,17.78 54.61,17.78 TP8.1@55.88,19.05 57.983,19.05 58.665,18.367 U6.11@58.967,18.367
P0.00: P6.1 P12.1 P17.2 SB4.2 | length 37.6
  Top Layer w0.152: v2@104.851,50.775 106.723,48.902 106.723,48.318 108.585,46.457 108.585,45.953 SB4.2@108.585,45.778
  Top Layer w0.381: P6.1@86.36,54.415 v1(86.36,55.88) P6.1@86.36,57.345 P17.2@86.36,59.69
  Mid-Layer 1 w0.152: v1(86.36,55.88) 86.36,52.577 87.934,51.003 104.026,51.003 104.227,51.204 104.578,51.204 104.902,50.879 v2(104.902,50.8) ; v2@104.851,50.775 v2@104.851,50.8
  Bottom Layer w0.381: P12.1@86.36,54.415 v1(86.36,55.88) P12.1@86.36,57.345
P0.00/XL1: SB2.2 SB4.1 U1.D2 | length 11.2
  Top Layer w0.145: 111.1,39.512 112.309,39.512 U1.D2@112.414,39.617
  Top Layer w0.152: SB4.1@108.585,45.154 108.585,44.432 108.029,44.432 107.703,44.107 107.703,42.418 107.195,41.91 107.195,40.479 107.716,39.958 110.642,39.958 111.077,39.523
P0.01: P6.2 P12.2 P17.4 SB3.2 | length 37.4
  Top Layer w0.152: v2(104.394,50.8) 104.394,50.673 106.426,48.641 106.426,45.953 SB3.2@106.426,45.778
  Top Layer w0.381: P6.2@83.82,54.415 v1(83.82,55.88) P6.2@83.82,57.345 P17.4@83.82,59.69
  Mid-Layer 1 w0.152: v1(83.82,55.88) 83.82,54.686 87.808,50.698 v2@104.318,50.698
  Bottom Layer w0.381: P12.2@83.82,54.415 v1(83.82,55.88) P12.2@83.82,57.345
P0.01/XL2: SB1.2 SB3.1 U1.F2 | length 11.9
  Top Layer w0.145: 110.922,39.222 112.309,39.222 U1.F2@112.414,39.117
  Top Layer w0.152: SB3.1@106.426,45.154 SB1.2@106.426,44.432 107.086,44.432 107.399,44.12 107.399,42.596 106.891,42.088 106.891,40.353 107.59,39.654 110.516,39.654 110.922,39.248 110.922,39.222
P0.02/AIN0: P4.8 P10.8 P16.16 U1.A12 | length 111.2
  Top Layer w0.152: P4.8@23.876,54.415 23.876,53.848 26.467,51.257 46.455,51.257 48.894,48.819 61.694,48.819 63.447,47.066 66.326,47.066 68.079,48.819 79.164,48.819 79.65,48.332 82.289,48.332 v2(82.333,48.376) ; v2(114.478,46.33) 114.702,46.106 114.702,41.33 114.914,41.119 U1.A12@114.914,40.867
  Top Layer w0.381: P4.8@23.876,54.415 v1(23.876,55.88) P4.8@23.876,57.345 P16.16@23.876,59.69
  Mid-Layer 1 w0.152: v2(82.333,48.376) 82.522,48.565 113.741,48.565 114.275,48.031 114.275,46.886 114.374,46.786 114.374,46.434 v2(114.478,46.33)
  Bottom Layer w0.381: P10.8@23.876,53.848 v1(23.876,55.88) P10.8@23.876,57.345
P0.03/AIN1: P2.1 P8.1 P14.2 TP42.1 U1.B13 | length 113.6
  Top Layer w0.152: TP42.1@95.885,25.781 96.69,24.976 96.69,24.369 96.146,23.825 v1(96.081,23.825)
  Top Layer w0.381: P14.2@50.8,3.81 P2.1@50.8,6.155 v1(50.8,7.62) P2.1@50.8,9.085
  Mid-Layer 1 w0.152: v1(101.676,48.014) 101.92,48.258 113.592,48.258 113.97,47.88 113.97,46.724 114.071,46.622 114.071,44.119 114.456,43.735 114.456,41.706 115.164,40.998 v2(115.164,40.367)
  Mid-Layer 2 w0.152: v1(50.8,7.62) 52.553,9.373 64.226,9.373 64.541,9.057 68.912,9.057 72.021,12.167 88.544,12.167 95.462,19.084 95.462,23.275 95.974,23.787 96.119,23.787 96.901,24.569 96.901,27.467 97.663,28.229 97.663,30.532 101.244,34.113 101.244,34.116 101.542,34.414 101.542,35.687 101.552,35.697 101.552,35.704 102.057,36.209 102.057,44.799 101.6,45.256 101.6,47.937 v1(101.676,48.014)
  Bottom Layer w0.381: P8.1@50.8,6.155 v1(50.8,7.62) P8.1@50.8,9.677
P0.04/AIN2: P2.2 P8.2 P14.4 TP43.1 U1.J1 U8.15 | length 96.4
  Top Layer w0.15: U1.J1@111.86,38.319 U1.J1@111.908,38.367
  Top Layer w0.152: U8.15@92.148,22.397 92.148,22.101 92.406,21.843 93.243,21.843 94.64,23.241 95.555,23.241 v1@95.872,22.924 ; TP43.1@95.885,27.686 96.825,26.746 96.825,25.425 96.988,25.262 96.988,23.989 v1@96.037,23.038 ; v1(102.083,35.484) 102.362,35.204 104.168,35.204 105.209,36.246 109.8,36.246 109.979,36.424 109.979,36.426 111.547,37.995 111.547,38.019 111.762,38.233 111.786,38.233 111.86,38.307 U1.J1@111.86,38.319 ; U1.J1@111.908,38.367 U1.J1@111.914,38.367
  Top Layer w0.381: P14.4@53.34,3.81 P2.2@53.34,6.155 v1(53.34,7.62) P2.2@53.34,9.085
  Mid-Layer 2 w0.152: v1(53.34,7.62) 54.788,9.068 64.1,9.068 64.415,8.753 69.038,8.753 72.147,11.862 73.33,11.862 88.671,11.862 95.766,18.957 95.766,22.818 v1(96.012,23.063) ; v1@96.041,23.034 96.612,23.606 96.612,23.853 97.203,24.444 97.203,25.017 97.206,25.019 97.206,27.341 97.968,28.103 97.968,30.405 102.083,34.52 v1(102.083,35.484)
  Bottom Layer w0.381: P8.2@53.34,6.155 v1(53.34,7.62) P8.2@53.34,9.085
P0.05/AIN3: P6.3 P12.3 P17.6 SB51.1 U1.K2 | length 96.3
  Top Layer w0.152: SB51.1@74.912,17.704 75.087,17.704 75.342,17.704 75.672,18.034 76.022,18.034 76.558,18.569 76.558,22.528 v1(76.276,22.809)
  Top Layer w0.381: P6.3@81.28,54.661 v1(81.28,55.88) P6.3@81.28,57.345 P17.6@81.28,59.69
  Mid-Layer 1 w0.152: v1@100.432,37.694 102.417,37.694 103.865,36.246 109.8,36.246 111.672,38.117 v2(112.414,38.117)
  Mid-Layer 2 w0.152: v1(76.276,22.809) 75.082,22.809 72.796,25.095 72.796,37.592 v1(72.669,37.719) 72.669,38.042 75.692,41.065 75.692,49.936 81.28,55.524 v1(81.28,55.88)
  Bottom Layer w0.152: v1(72.669,37.719) 72.771,37.617 78.486,37.617 80.289,35.814 85.227,35.814 86.091,36.678 87.655,36.678 88.214,36.119 98.026,36.119 99.626,37.719 v1(100.406,37.719)
  Bottom Layer w0.381: P12.3@81.28,54.415 v1(81.28,55.88) P12.3@81.28,57.345
P0.06: P6.4 P12.4 P17.8 SB53.1 U1.L1 | length 91.5
  Top Layer w0.15: 109.804,35.941 109.925,35.941 110.282,36.299 110.282,36.3 111.85,37.867 U1.L1@111.914,37.867
  Top Layer w0.152: v1(99.847,37.186) 100.627,37.186 101.244,36.568 101.244,35.33 101.675,34.9 104.294,34.9 105.335,35.941 109.804,35.941
  Top Layer w0.203: v1(72.459,20.897) 72.459,21.288 SB53.1@72.459,21.641
  Top Layer w0.381: P6.4@78.74,54.415 v1(78.74,55.88) P6.4@78.74,57.345 P17.8@78.74,59.69
  Mid-Layer 2 w0.152: v1(72.459,20.897) 72.492,20.93 72.492,36.805 v1(72.136,37.16) 72.136,37.94 75.387,41.191 75.387,50.063 78.74,53.415 v1(78.74,55.88)
  Bottom Layer w0.152: v1(72.136,37.16) 73.339,37.16 73.491,37.313 78.351,37.313 80.155,35.509 85.353,35.509 86.217,36.373 87.529,36.373 88.088,35.814 98.153,35.814 99.524,37.186 v1(99.847,37.186)
  Bottom Layer w0.381: P12.4@78.74,54.415 v1(78.74,55.88) P12.4@78.74,57.345
P0.07: P6.5 P12.5 P17.10 P25.12 U1.M2 U8.1 | length 92.9
  Top Layer w0.152: P25.12@78.74,34.245 v1(78.74,36.17) ; U8.1@92.773,23.022 93.99,23.022 94.743,23.774 v1(94.844,23.774)
  Top Layer w0.381: P6.5@76.2,54.61 v1(76.2,55.88) P6.5@76.2,57.345 P17.10@76.2,59.69
  Mid-Layer 1 w0.152: v1(100.406,36.652) 103.031,36.652 103.742,35.941 109.927,35.941 111.603,37.617 v2(112.414,37.617)
  Mid-Layer 2 w0.152: v1(71.603,36.601) 71.603,37.897 75.082,41.377 75.082,50.189 76.2,51.306 v1(76.2,55.88) ; v1(94.844,23.774) 94.844,24.544 95.987,25.687 95.987,27.846 96.749,28.608 96.749,30.91 99.009,33.171 99.009,36.035 99.626,36.652 v1(100.406,36.652)
  Bottom Layer w0.152: v1(71.603,36.601) 73.211,36.601 73.618,37.008 77.579,37.008 79.382,35.204 85.479,35.204 86.343,36.068 87.403,36.068 87.962,35.509 98.279,35.509 99.422,36.652 v1(100.406,36.652)
  Bottom Layer w0.381: P12.5@76.2,54.415 v1(76.2,55.88) P12.5@76.2,57.345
